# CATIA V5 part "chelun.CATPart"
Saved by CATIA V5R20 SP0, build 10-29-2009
Part number: chelun
Bounding box of the stored display mesh (mm): x -266 to 266, y -114 to 114, z -266 to 266
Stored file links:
  C:\Users\DELL\AppData\Local\Temp\Rar$DIa0.776\chelun.CATPart
  C:\Program Files (x86)\Dassault Systemes\B20\intel_a\startup\materials\Catalog.CATMaterial
  C:\Program Files (x86)\Dassault Systemes\B20\intel_a\startup\materials\dashboard.jpg
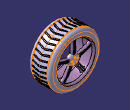
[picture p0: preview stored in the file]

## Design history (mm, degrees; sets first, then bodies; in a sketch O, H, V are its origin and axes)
Body1 (main body), material "无"
  Sketch1 on xy-plane, origin (0, 0, 0), H (1, 0, 0), V (0, 1, 0)
    point P1 (-190, 0)
    line L1 (-190, 0) -> (-190, 90)
    point P2 (-190, 90)
    arc A1 centre (-215, 90) radius 25 from (-190, 90) to (-200, 110) ccw
    point P4 (-200, 110)
    point P5 (-200, -110)
    point P6 (-190, -90)
    arc A2 centre (-215, -90) radius 25 from (-190, -90) to (-200, -110) cw
    point P8 (-190, 0)
    line L2 (-190, 0) -> (-190, -90)
    length L1 = 90
    radius A1 = 25
    distance P4 V = 200
    distance L1 V = 190
    coincidence: P1 H
    vertical: L1 V
    tangency: A1 L1
    symmetry: P4 P5 H, P2 P6 H, A1 A2 H, P1 P8 H, L1 L2 H
  Revol1: Element1 Sketch1, Line Y axis, Angle1 360
  Plane1: type Offset, RefPlane zx-plane, Offset 70
  Point1: (0, 70, 0)
  Plane2: type OffsetPt, RefPlane xy-plane, RefPoint Point1
  Sketch2 on Plane2, origin (0, 0, 0), H (1, 0, 0), V (0, 1, 0)
    spline S1 through (0, 102.229) (24.3007, 100.035) (42.6524, 95.2257) (54.3355, 87.181) (59.9989, 70.3635)
    reference projected point E1 (0, 70) from Point1
    point P1 (0, 102.229)
    point P2 (59.9989, 70.3635)
    distance P2 E1 = 60
    coincidence: P1 V
  Revol2: Element1 Sketch2, Line Y axis, Angle1 360
  Plane3: type Offset, RefPlane Plane2, Offset 40
  Sketch3 on Plane3, origin (0, 0, 40), H (1, 0, 0), V (0, 1, 0)
    spline S1 through (15, 73.3635) (10.4072, 84.0351) (0, 87.4818)
    reference projected line E1 (59.9989, 70.3635) -> (-59.9989, 70.3635) from edge of Revol2
    spline S2 through (-15, 73.3635) (-10.4072, 84.0351) (0, 87.4818)
    point P1 (0, 87.4818)
    point P2 (15, 73.3635)
    point P3 (0, 87.4818)
    point P4 (-15, 73.3635)
    point P5 (10.4072, 84.0351)
    point P6 (-10.4072, 84.0351)
    distance P2 V = 15
    distance P2 E1 = 3
    coincidence: P1 V
    symmetry: S1 S2 V, P1 P3 V, P2 P4 V, P5 P6 V
  Plane4: type Offset, RefPlane Plane2, Offset 207
  Sketch4 on Plane4, origin (0, 0, 207), H (1, 0, 0), V (0, 1, 0)
    spline S1 through (30, 73.3635) (25.6993, 83.9648) (18.5063, 89.2043) (9.7407, 91.1467) (0, 91.9332)
    reference projected line E1 (59.9989, 70.3635) -> (-59.9989, 70.3635) from edge of Revol2
    spline S2 through (-30, 73.3635) (-25.6993, 83.9648) (-18.5063, 89.2043) (-9.7407, 91.1467) (0, 91.9332)
    point P1 (0, 91.9332)
    point P2 (30, 73.3635)
    point P3 (0, 91.9332)
    point P4 (-30, 73.3635)
    point P5 (9.7407, 91.1467)
    point P6 (-9.7407, 91.1467)
    point P7 (18.5063, 89.2043)
    point P8 (-18.5063, 89.2043)
    point P9 (25.6993, 83.9648)
    point P10 (-25.6993, 83.9648)
    distance P2 V = 30
    distance P2 E1 = 3
    coincidence: P1 V
    symmetry: S1 S2 V, P1 P3 V, P2 P4 V, P5 P6 V, P7 P8 V, P9 P10 V
  Line1: type PtPt, FirstPoint Sketch3.P2, SecondPoint Sketch4.P2
  Line2: type PtPt, FirstPoint Sketch3.P4, SecondPoint Sketch4.P4
  Point2: type OnCurve, Support Sketch3, Ratio 0.3
  Point3: type OnCurve, Support Sketch3, Ratio 0.7
  Point4: type OnCurve, Support Sketch4, Ratio 0.3
  Point5: type OnCurve, Support Sketch4, Ratio 0.7
  Line3: type PtPt, FirstPoint Point3, SecondPoint Point5
  Line4: type PtPt, FirstPoint Point2, SecondPoint Point4
  Plane5: type 2Lines, Element1 Line1, Element2 Line2
  Sketch5 on Plane5, origin (0, 73.3635, 0), H (1, 0, 0), V (0, 0, 1)
    projected point E1 (30, 207) from Sketch4.P2
    projected point E2 (15, 40) from Sketch3.P2
    spline S1 through (30, 207) (27.2239, 193.724) (23.6553, 181.3517) (18.1652, 164.3055) (16.2436, 152.2082) (15, 132.1376) (15, 114.8165) (16.2436, 98.595) (17.3065, 87.7687) (17.3065, 68.6615) (15, 40)
    point P1 (30, 207)
    point P2 (15, 40)
    coincidence: P1 E1, P2 E2
  Plane6: type 2Lines, Element1 Line2, Element2 Line1
  Sketch6 on Plane6, origin (0, 73.3635, 0), H (-1, 0, 0), V (0, 0, 1)
    frozenspline C1
  Point6: type OnCurve, Support Line3, Ratio 0.3
  Point7: (-3, 13, 28), relative to Point6
  Point8: (0, 8, -5), relative to Point6
  Point9: (4, 8, 70), relative to Point6
  Line5: type PtPt, FirstPoint Point3, SecondPoint Point5
  Point10: type OnCurve, Support Line4, Ratio 0.3
  Point11: (3, 13, 30), relative to Point9
  Point12: (-3, 8, 72), relative to Point9
  Curve1: Elements (Point3; Point8; Point9; Point5)
  Symmetry1: ToTransfor Curve1, Reference yz-plane
  Loft1: Sections (Sketch3; Sketch4), Guides (Sketch6; Curve1; Symmetry1; Sketch5)
  Split1: ToCut Loft1, Cutting Revol2
  Split2: ToCut Split1, Cutting Revol1
  Set1
    ThickSurface1: Surface Split2, TopOffset 3, BotOffset 3
    ThickSurface2: Surface Revol1, TopOffset 5, BotOffset 0.5
    Plane7: type Offset, RefPlane Plane1, Offset 50
    Sketch7 on Plane7, origin (0, 120, 0), H (-1, 0, 0), V (0, 0, 1)
      line L1 (-4.5105, 68.1068) -> (4.4895, 68.1068)
      arc A1 centre (4.4895, 71.1068) radius 3 from (4.4895, 68.1068) to (7.4516, 71.5822) ccw
      arc A2 centre (303.6616, 119.1177) radius 300 from (7.4516, 71.5822) to (7.5486, 167.2538) cw
      arc A3 centre (4.5875, 167.7352) radius 3 from (7.5486, 167.2538) to (4.5875, 170.7352) ccw
      line L2 (4.5875, 170.7352) -> (-4.4125, 170.7352)
      arc A4 centre (-4.4125, 167.7352) radius 3 from (-4.4125, 170.7352) to (-7.3746, 167.2598) ccw
      arc A5 centre (-303.5846, 119.7243) radius 300 from (-7.3746, 167.2598) to (-7.4716, 71.5882) cw
      arc A6 centre (-4.5105, 71.1068) radius 3 from (-7.4716, 71.5882) to (-4.5105, 68.1068) ccw
      radius A4 = 3
      radius A6 = 3
      radius A1 = 3
      radius A3 = 3
      radius A5 = 300
      radius A2 = 300
      distance A6 A1 = 15
      distance A4 A3 = 15
      horizontal: L1 H, L2 H
      tangency: A1 L1, A2 A1, A3 A2, L2 A3, A4 L2, A5 A4, A6 A5, A6 L1
    Extrude1: Element1 Sketch7, Lim1 57, Lim2 0, Direction Plane7
    Remove1: tool Extrude1
    CircPattern1: of Remove1, instances 5, angular step 72, axis from Y axis
    Sketch8 on yz-plane, origin (0, 0, 0), H (0, 1, 0), V (0, 0, 1)
      point P1 (-109.6, 200.3)
      line L1 (-109.6, 200.3) -> (-107.6515, 233.9053)
      point P2 (-107.6515, 233.9053)
      arc A1 centre (-80, 232.302) radius 27.698 from (-107.6515, 233.9053) to (-80, 260) cw
      point P4 (-80, 260)
      line L2 (-80, 260) -> (0, 260)
      point P5 (0, 260)
      reference projected line E1 (-90, 0) -> (0, 0) from Sketch1.L2
      point P6 (107.6515, 233.9053)
      point P7 (109.6, 200.3)
      line L3 (109.6, 200.3) -> (107.6515, 233.9053)
      point P8 (80, 260)
      arc A2 centre (80, 232.302) radius 27.698 from (107.6515, 233.9053) to (80, 260) ccw
      point P10 (0, 260)
      line L4 (80, 260) -> (0, 260)
      distance L2 E1 = 260
      length L2 = 80
      tangency: A1 L1, L2 A1
      coincidence: P5 V
      horizontal: L2 H
      symmetry: P2 P6 V, P1 P7 V, L1 L3 V, P4 P8 V, A1 A2 V, P5 P10 V, L2 L4 V
    Revol3: Element1 Sketch8, Line Y axis, Angle1 360
  ThickSurface3: Surface Revol3, TopOffset 3, BotOffset 2
  Plane8: type Offset, RefPlane zx-plane, Offset 70
  Point13: type OnCurve, Support Sketch8, Ratio 0.25
  Plane9: type 1Curve, Element1 Sketch8
  Sketch9 on Plane9, origin (0, 0, 0), H (0, 1, 0), V (0, 0, 1)
    line L1 (74.2437, 266.504) -> (76.8265, 261.7146)
    line L2 (76.8265, 261.7146) -> (81.7191, 261.7146)
    line L3 (81.7191, 261.7146) -> (83.2146, 266.504)
    line L4 (83.2146, 266.504) -> (74.2437, 266.504)
    horizontal: L2 H, L4 H
    coincidence: L3 O
  Sketch10 on Plane8, origin (0, 70, 0), H (-1, 0, 0), V (0, 0, 1)
    circle A1 centre (0, 0) radius 249.8182
  Groove1: profile Sketch9, axis Y axis, angle 360
  Sketch11 on Plane9, origin (0, 0, 0), H (0, 1, 0), V (0, 0, 1)
    line L1 (-77.0716, 268.5286) -> (-70.0732, 268.5286)
    line L2 (-70.0732, 268.5286) -> (-70.0732, 261.5191)
    line L3 (-70.0732, 261.5191) -> (-77.0716, 261.5191)
    line L4 (-77.0716, 261.5191) -> (-77.0716, 268.5286)
    horizontal: L1 H, L3 H
    vertical: L2 V, L4 V
  Groove2: profile Sketch11, axis Y axis, angle 360
  Plane10: type Offset, RefPlane xy-plane, Offset 266
  Sketch12 on Plane10, origin (0, 0, 266), H (1, 0, 0), V (0, 1, 0)
    line L1 (-6.979, 70.7261) -> (-1.1835, 72.279)
    line L2 (2.4908, 70.1577) -> (19.0576, 8.3294)
    line L3 (16.9363, 4.6551) -> (11.1407, 3.1022)
    line L4 (7.4665, 5.2235) -> (-9.1003, 67.0519)
    arc A1 centre (-6.2026, 67.8283) radius 3 from (-6.979, 70.7261) to (-9.1003, 67.0519) ccw
    arc A2 centre (-0.407, 69.3812) radius 3 from (-1.1835, 72.279) to (2.4908, 70.1577) cw
    arc A3 centre (16.1598, 7.5529) radius 3 from (19.0576, 8.3294) to (16.9363, 4.6551) cw
    arc A4 centre (10.3643, 6) radius 3 from (11.1407, 3.1022) to (7.4665, 5.2235) cw
    reference projected line E1 (-263, 0) -> (263, 0) from edge [face of ThickSurface3 | face of ThickSurface3]
    reference projected line E2 (-263, 0) -> (263, 0) from edge [face of ThickSurface3 | face of ThickSurface3]
    radius A1 = 3
    radius A2 = 3
    radius A3 = 3
    radius A4 = 3
    distance L2 L4 = 12
    angle E1 L2 = 105
    distance E2 A4 = 3
    perpendicularity: L3 L2
    tangency: A1 L1, A1 L4, A2 L1, A2 L2, A3 L2, A3 L3, A4 L3, A4 L4
    parallelism: L3 L1
  Set2
    Extrude2: Element1 Sketch12, Lim1 6, Lim2 0
    Draft1: PullDir face of Extrude2, Angle 10, SupportToDraft (face of Extrude2 from Sketch12.L4; face of Extrude2 from Sketch12.A1; face of Extrude2 from Sketch12.L1; face of Extrude2 from Sketch12.A2; face of Extrude2 from Sketch12.L2; face of Extrude2 from Sketch12.A3; face of Extrude2 from Sketch12.L3; face of Extrude2 from Sketch12.A4), Neutral face of Extrude2
    Fillet1: radius 2, on face of Extrude2
    CircPattern2: of Fillet1, instances 36, angular step 10, axis from Y axis
    Symmetry2: ToTransfor CircPattern2, Reference zx-plane
  ThickSurface4: Surface Revol2, TopOffset 3, BotOffset 3
  Sketch13 on {plane type Tangent, Support face of ThickSurface4, RefPoint {point type OnSurface, Support face of ThickSurface4, RefPoint {point stored without definition}, Length 0, Direction (0, 35.8398, -999.3575)}}, origin (27.9878, 102.384, 5.7182), H (0.985, -0.1727, -0.0062), V (0, -0.0358, 0.9994)
    point P1 (0, 0)
  Hole1: placed by Sketch13, at (27.9878, 102.384, 5.7182) direction (-0.1728, -0.9843, -0.0353), diameter 15, through (limit type 6), counterbore diameter 20, counterbore depth 3
  CircPattern3: of Hole1, instances 5, angular step 72, axis from Y axis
